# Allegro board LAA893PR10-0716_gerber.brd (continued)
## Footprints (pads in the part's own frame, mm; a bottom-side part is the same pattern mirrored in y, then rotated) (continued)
BELLW_80148-3221_67P-T
  round 1.092 hole 1.092 unplated: (-0.75,-5.275)
  round 1.6 hole 1.6 unplated: (19.25,-5.275)
  oval 0.305x1.549 smd: 1(0,0) 2(0.25,-7.55) 3(0.5,0) 4(0.75,-7.55) 5(1,0) 6(1.25,-7.55) 7(1.5,0) 8(3.75,-7.55) 9(4,0) 10(4.25,-7.55) 11(4.5,0) 12(4.75,-7.55) 13(5,0) 14(5.25,-7.55) 15(5.5,0) 16(5.75,-7.55) 17(6,0) 18(6.25,-7.55) 19(6.5,0) 20(6.75,-7.55) 21(7,0) 22(7.25,-7.55) 23(7.5,0) 24(7.75,-7.55) 25(8,0) 26(8.25,-7.55) 27(8.5,0) 28(8.75,-7.55) 29(9,0) 30(9.25,-7.55) 31(9.5,0) 32(9.75,-7.55) 33(10,0) 34(10.25,-7.55) 35(10.5,0) 36(10.75,-7.55) 37(11,0) 38(11.25,-7.55) 39(11.5,0) 40(11.75,-7.55) 41(12,0) 42(12.25,-7.55) 43(12.5,0) 44(12.75,-7.55) 45(13,0) 46(13.25,-7.55) 47(13.5,0) 48(13.75,-7.55) 49(14,0) 50(14.25,-7.55) 51(14.5,0) 52(14.75,-7.55) 53(15,0) 54(15.25,-7.55) 55(15.5,0) 56(15.75,-7.55) 57(16,0) 58(16.25,-7.55) 59(16.5,0) 60(16.75,-7.55) 61(17,0) 62(17.25,-7.55) 63(17.5,0) 64(17.75,-7.55) 65(18,0) 66(18.25,-7.55) 67(18.5,0)
  rect 1.194x2.743 smd: 68(-1.1,-0.775) 69(19.6,-0.775)
BQ24715URUYR_WQFN28_4X4
  oval 0.889x0.203 smd: 1(0,0) 2(0,-0.4) 3(0,-0.8) 4(0,-1.2) 5(0,-1.6) 6(0,-2) 7(0,-2.4) 15(4.1,-2.4) 16(4.1,-2) 17(4.1,-1.6) 18(4.1,-1.2) 19(4.1,-0.8) 20(4.1,-0.4) 21(4.1,0)
  oval 0.203x0.889 smd: 8(0.85,-3.25) 9(1.25,-3.25) 10(1.65,-3.25) 11(2.05,-3.25) 12(2.45,-3.25) 13(2.85,-3.25) 14(3.25,-3.25) 22(3.25,0.85) 23(2.85,0.85) 24(2.45,0.85) 25(2.05,0.85) 26(1.65,0.85) 27(1.25,0.85) 28(0.85,0.85)
  rect 2.591x2.591 smd: 29(2.05,-1.2)
C-K_26210-8K1A-02_9P-T
  round 1.118 hole 0.711: 1(0,0) 2(-2.5,0) 3(-4.5,0) 4(-7,0) 5(-7.5,-1.5) 6(-5.5,-1.5) 7(-3.5,-1.5) 8(-1.5,-1.5) 9(0.5,-1.5)
  oval 1.549x3.353 hole 0.787x2.591: 10(4.35,-2.43) 11(-11.35,-2.43)
  oval 1.549x2.464 hole 0.787x1.702: 12(-11.35,-9.23) 13(4.35,-9.23)
C_0402
  rect 0.508x0.559 smd: 1(0,0) 2(0.914,0)
C_0603
  rect 0.635x0.889 smd: 1(0,0) 2(1.397,0)
C_0805
  rect 0.813x1.397 smd: 1(0,0) 2(1.702,0)
C_1206
  rect 1.016x1.651 smd: 1(0,0) 2(2.667,0)
C_1808
  rect 1.041x2.311 smd: 1(0,0) 2(4.35,0)
C_APXK6R3ARA221MF451
  oval 3.15x1.6 smd: 1(0,0) 2(5.05,0)
C_D
  rect 2.388x2.896 smd: 1(0,0) 2(6.1,0)
C_D2
  rect 2.388x2.794 smd: 1(0,0) 2(6.4,0)
C_D3
  rect 2.388x2.794 smd: 1(0,0) 2(6.4,0)
CONCR_099BKAC19YBLCNF_19P-T
  round 0.813 hole 0.508: 1(0,0) 2(0.5,1.5) 3(1,0) 4(1.5,1.5) 5(2,0) 6(2.5,1.5) 7(3,0) 8(3.5,1.5) 9(4,0) 10(4.5,1.5) 11(5,0) 12(5.5,1.5) 13(6,0) 14(6.5,1.5) 15(7,0) 16(7.5,1.5) 17(8,0) 18(8.5,1.5) 19(9,0)
  oval 1.397x3.15 hole 0.787x2.54: 20(-2.75,0.9) 21(11.75,0.9)
  oval 1.803x2.794 hole 0.787x1.803: 22(-4.75,-6.08) 23(13.75,-6.08)
CSD97374CQ4M_SON8_3P5X4P5
  oval 0.203x0.889 smd: 1(0,0) 2(0.4,0) 3(0.8,0) 6(0.8,3.5) 7(0.4,3.5) 8(0,3.5)
  custom 0.225x0.225 smd: 4(2.2,0.262) 5(2.2,3.238)
  rect 4.039x2.21 smd: 9(1.6,1.75)
DCX124EK-7-F_SC74R-6
  oval 0.559x0.787 smd: 1(0,0) 2(-0.95,0) 3(-1.9,0) 4(-1.9,2.4) 5(-0.95,2.4) 6(0,2.4)
DDTA114EUA-7-F_SOT323-3
  oval 0.813x0.914 smd: 1(0,0) 2(0.65,1.6) 3(-0.65,1.6)
DEREN_40-42251-01001RHF_10P-T
  oval 0.838x2.21 smd: 1(0,0.1) 2(1.5,0.1) 3(3,0.1) 4(4.5,0.1) 5(6,0.1) 6(7.5,0.1) 7(9,0.1) 8(10.5,0.1) 9(12,0.1) 10(13.5,0.1)
  custom 0.75x0.75 smd: 11(-3.4,-3.15) 12(16.9,-3.15)
DMN65D8LW-7_SOT323-3
  oval 0.711x0.889 smd: 1(0,0) 2(-0.65,-1.9) 3(0.65,-1.9)
DMN66D0LDW-7_SOT363-6
  oval 0.432x0.61 smd: 1(0,0) 2(0.65,0) 3(1.3,0) 4(1.3,1.9) 5(0.65,1.9) 6(0,1.9)
E-T_6700K-Y20N-00L_20P
  oval 0.61x1.499 smd: 1(0,0) 2(-0.5,-2.8) 3(-1,0) 4(-1.5,-2.8) 5(-2,0) 6(-2.5,-2.8) 7(-3,0) 8(-3.5,-2.8) 9(-4,0) 10(-4.5,-2.8) 11(-5,0) 12(-5.5,-2.8) 13(-6,0) 14(-6.5,-2.8) 15(-7,0) 16(-7.5,-2.8) 17(-8,0) 18(-8.5,-2.8) 19(-9,0) 20(-9.5,-2.8)
  rect 0.787x1.499 smd: 21(1,0) 22(1,-2.8) 23(-10.5,0) 24(-10.5,-2.8)
E-T_6705K-Y10N-00L_10P-T
  oval 0.305x1.092 smd: 1(0,0) 2(0.5,0) 3(1,0) 4(1.5,0) 5(2,0) 6(2.5,0) 7(3,0) 8(3.5,0) 9(4,0) 10(4.5,0)
  rect 0.991x2.007 smd: 11(-2.1,-3.15) 12(6.6,-3.15)
E-T_6705K-Y16N-00L_16P
  oval 0.305x1.092 smd: 1(0,0) 2(0.5,0) 3(1,0) 4(1.5,0) 5(2,0) 6(2.5,0) 7(3,0) 8(3.5,0) 9(4,0) 10(4.5,0) 11(5,0) 12(5.5,0) 13(6,0) 14(6.5,0) 15(7,0) 16(7.5,0)
  rect 0.991x2.007 smd: 17(-2.1,-3.15) 18(9.6,-3.15)
ECE1099-FZG_QFN40_6X6
  oval 0.254x1.041 smd: 1(0,0) 2(0.5,0) 3(1,0) 4(1.5,0) 5(2,0) 6(2.5,0) 7(3,0) 8(3.5,0) 9(4,0) 10(4.5,0) 21(4.5,5.95) 22(4,5.95) 23(3.5,5.95) 24(3,5.95) 25(2.5,5.95) 26(2,5.95) 27(1.5,5.95) 28(1,5.95) 29(0.5,5.95) 30(0,5.95)
  oval 1.041x0.254 smd: 11(5.225,0.725) 12(5.225,1.225) 13(5.225,1.725) 14(5.225,2.225) 15(5.225,2.725) 16(5.225,3.225) 17(5.225,3.725) 18(5.225,4.225) 19(5.225,4.725) 20(5.225,5.225) 31(-0.725,5.225) 32(-0.725,4.725) 33(-0.725,4.225) 34(-0.725,3.725) 35(-0.725,3.225) 36(-0.725,2.725) 37(-0.725,2.225) 38(-0.725,1.725) 39(-0.725,1.225) 40(-0.725,0.725)
  rect 4.089x4.089 smd: 41(2.25,2.975)
FDV301N-G_SOT23-3
  oval 1.016x1.524 smd: 1(0,0) 2(0.965,2.083) 3(-0.965,2.083)
FIDUCIAL_C40M80
  round 1.016 smd: 1(0,0)
G547I2P81U_MSOP8
  oval 0.381x1.549 smd: 1(0,0) 2(0.65,0) 3(1.3,0) 4(1.95,0) 5(1.95,4.37) 6(1.3,4.37) 7(0.65,4.37) 8(0,4.37)
H_2P3
  round 2.819 hole 2.311: 1(0,0)
H_2P6N
  round 2.591 hole 2.591 unplated: (0,0)
H_3P2
  round 3.708 hole 3.2: 1(0,0)
H_3P3
  round 3.81 hole 3.302: 1(0,0)
H_3P5
  round 4.013 hole 3.505: 1(0,0)
H_3P6
  round 4.115 hole 3.607: 1(0,0)
H_5P2X2P6N
  oval 5.207x2.591 hole 5.207x2.591 unplated: (0,0)
H_5P5N
  round 5.512 hole 5.512 unplated: (0,0)
HB_A531015-SCHR21_10P
  oval 0.305x0.889 smd: 1(0,0) 2(0.5,0) 3(1,0) 4(1.5,0) 5(2,0) 6(2.5,0) 7(3,0) 8(3.5,0) 9(4,0) 10(4.5,0)
  rect 0.991x2.007 smd: 11(6.6,-3.05) 12(-2.1,-3.05)
JUMP_43X39
  custom 0.191x0.191 smd: 1(0,0) 2(0.914,0)
JUMP_43X79
  custom 0.188x0.188 smd: 1(0,0) 2(1.1,0)
JUMP_43X118
  custom 0.187x0.187 smd: 1(0,0) 2(1.1,0)
JUMP_43X118-NPM
  custom 0.187x0.187 smd: 1(0,0) 2(1.1,0)
KC_FBMA-L11-453215800LMA90T_2P
  rect 1.803x3.404 smd: 1(0,0) 2(3.8,0)
KNOW_SPM1437HM4H-6_6P
  round 0.914 smd: 1(0,0) 2(0,-1.65) 3(0,-3.3) 4(2.34,-3.3) 5(2.34,-1.65)
  oval 0.914x1.194 smd rot 135: 6(2.24,-0.1)
L2N7002WT1G_SC-70-3
  oval 0.711x0.889 smd: 1(0,0) 2(-0.65,-1.9) 3(0.65,-1.9)
L03ESDL5V0CC3-2_SOT23-3
  oval 1.016x1.524 smd: 1(0,0) 2(0.965,2.083) 3(-0.965,2.083)
L05ESDL5V0NA-4_SLP2510P8-10-9
  rect 0.203x0.686 smd: 1(0,0) 2(-0.5,0) 4(-1.5,0) 5(-2,0) 6(-2,-0.875) 7(-1.5,-0.875) 8(-0.5,-0.875) 9(0,-0.875)
  rect 0.406x1.549 smd: 3(-1,-0.437)
L_5X5X3_M_2P
  rect 2.159x2.794 smd: 1(0,0) 2(4.35,0)
L_5X5X3_M_2P-NPM
  rect 2.159x2.794 smd: 1(0,0) 2(4.35,0)
LCN_DAN06-K4406-0103_204P
  round 1.092 hole 1.092 unplated: (-65.05,-4.1)
  round 1.6 hole 1.6 unplated: (1.75,-4.1)
  oval 0.356x2.007 smd: 1(0,0) 2(-0.3,-8.2) 3(-0.6,0) 4(-0.9,-8.2) 5(-1.2,0) 6(-1.5,-8.2) 7(-1.8,0) 8(-2.1,-8.2) 9(-2.4,0) 10(-2.7,-8.2) 11(-3,0) 12(-3.3,-8.2) 13(-3.6,0) 14(-3.9,-8.2) 15(-4.2,0) 16(-4.5,-8.2) 17(-4.8,0) 18(-5.1,-8.2) 19(-5.4,0) 20(-5.7,-8.2) 21(-6,0) 22(-6.3,-8.2) 23(-6.6,0) 24(-6.9,-8.2) 25(-7.2,0) 26(-7.5,-8.2) 27(-7.8,0) 28(-8.1,-8.2) 29(-8.4,0) 30(-8.7,-8.2) 31(-9,0) 32(-9.3,-8.2) 33(-9.6,0) 34(-9.9,-8.2) 35(-10.2,0) 36(-10.5,-8.2) 37(-10.8,0) 38(-11.1,-8.2) 39(-11.4,0) 40(-11.7,-8.2) 41(-12,0) 42(-12.3,-8.2) 43(-12.6,0) 44(-12.9,-8.2) 45(-13.2,0) 46(-13.5,-8.2) 47(-13.8,0) 48(-14.1,-8.2) 49(-14.4,0) 50(-14.7,-8.2) 51(-15,0) 52(-15.3,-8.2) 53(-15.6,0) 54(-15.9,-8.2) 55(-16.2,0) 56(-16.5,-8.2) 57(-16.8,0) 58(-17.1,-8.2) 59(-17.4,0) 60(-17.7,-8.2) 61(-18,0) 62(-18.3,-8.2) 63(-18.6,0) 64(-18.9,-8.2) 65(-19.2,0) 66(-19.5,-8.2) 67(-19.8,0) 68(-20.1,-8.2) 69(-20.4,0) 70(-20.7,-8.2) 71(-21,0) 72(-21.3,-8.2) 73(-24,0) 74(-24.3,-8.2) 75(-24.6,0) 76(-24.9,-8.2) 77(-25.2,0) 78(-25.5,-8.2) 79(-25.8,0) 80(-26.1,-8.2) 81(-26.4,0) 82(-26.7,-8.2) 83(-27,0) 84(-27.3,-8.2) 85(-27.6,0) 86(-27.9,-8.2) 87(-28.2,0) 88(-28.5,-8.2) 89(-28.8,0) 90(-29.1,-8.2) 91(-29.4,0) 92(-29.7,-8.2) 93(-30,0) 94(-30.3,-8.2) 95(-30.6,0) 96(-30.9,-8.2) 97(-31.2,0) 98(-31.5,-8.2) 99(-31.8,0) 100(-32.1,-8.2) 101(-32.4,0) 102(-32.7,-8.2) 103(-33,0) 104(-33.3,-8.2) 105(-33.6,0) 106(-33.9,-8.2) 107(-34.2,0) 108(-34.5,-8.2) 109(-34.8,0) 110(-35.1,-8.2) 111(-35.4,0) 112(-35.7,-8.2) 113(-36,0) 114(-36.3,-8.2) 115(-36.6,0) 116(-36.9,-8.2) 117(-37.2,0) 118(-37.5,-8.2) 119(-37.8,0) 120(-38.1,-8.2) 121(-38.4,0) 122(-38.7,-8.2) 123(-39,0) 124(-39.3,-8.2) 125(-39.6,0) 126(-39.9,-8.2) 127(-40.2,0) 128(-40.5,-8.2) 129(-40.8,0) 130(-41.1,-8.2) 131(-41.4,0) 132(-41.7,-8.2) 133(-42,0) 134(-42.3,-8.2) 135(-42.6,0) 136(-42.9,-8.2) 137(-43.2,0) 138(-43.5,-8.2) 139(-43.8,0) 140(-44.1,-8.2) 141(-44.4,0) 142(-44.7,-8.2) 143(-45,0) 144(-45.3,-8.2) 145(-45.6,0) 146(-45.9,-8.2) 147(-46.2,0) 148(-46.5,-8.2) 149(-46.8,0) 150(-47.1,-8.2) 151(-47.4,0) 152(-47.7,-8.2) 153(-48,0) 154(-48.3,-8.2) 155(-48.6,0) 156(-48.9,-8.2) 157(-49.2,0) 158(-49.5,-8.2) 159(-49.8,0) 160(-50.1,-8.2) 161(-50.4,0) 162(-50.7,-8.2) 163(-51,0) 164(-51.3,-8.2) 165(-51.6,0) 166(-51.9,-8.2) 167(-52.2,0) 168(-52.5,-8.2) 169(-52.8,0) 170(-53.1,-8.2) 171(-53.4,0) 172(-53.7,-8.2) 173(-54,0) 174(-54.3,-8.2) 175(-54.6,0) 176(-54.9,-8.2) 177(-55.2,0) 178(-55.5,-8.2) 179(-55.8,0) 180(-56.1,-8.2) 181(-56.4,0) 182(-56.7,-8.2) 183(-57,0) 184(-57.3,-8.2) 185(-57.6,0) 186(-57.9,-8.2) 187(-58.2,0) 188(-58.5,-8.2) 189(-58.8,0) 190(-59.1,-8.2) 191(-59.4,0) 192(-59.7,-8.2) 193(-60,0) 194(-60.3,-8.2) 195(-60.6,0) 196(-60.9,-8.2) 197(-61.2,0) 198(-61.5,-8.2) 199(-61.8,0) 200(-62.1,-8.2) 201(-62.4,0) 202(-62.7,-8.2) 203(-63,0) 204(-63.3,-8.2)
  rect 3.505x4.597 smd: 205(1.15,7.9) 206(-64.45,7.9)
LCN_DAN06-K4406-0103_204P-S
  round 1.092 hole 1.092 unplated: (-65.05,-4.1)
  round 1.6 hole 1.6 unplated: (1.75,-4.1)
  oval 0.356x2.007 smd: 1(0,0) 2(-0.3,-8.2) 3(-0.6,0) 4(-0.9,-8.2) 5(-1.2,0) 6(-1.5,-8.2) 7(-1.8,0) 8(-2.1,-8.2) 9(-2.4,0) 10(-2.7,-8.2) 11(-3,0) 12(-3.3,-8.2) 13(-3.6,0) 14(-3.9,-8.2) 15(-4.2,0) 16(-4.5,-8.2) 17(-4.8,0) 18(-5.1,-8.2) 19(-5.4,0) 20(-5.7,-8.2) 21(-6,0) 22(-6.3,-8.2) 23(-6.6,0) 24(-6.9,-8.2) 25(-7.2,0) 26(-7.5,-8.2) 27(-7.8,0) 28(-8.1,-8.2) 29(-8.4,0) 30(-8.7,-8.2) 31(-9,0) 32(-9.3,-8.2) 33(-9.6,0) 34(-9.9,-8.2) 35(-10.2,0) 36(-10.5,-8.2) 37(-10.8,0) 38(-11.1,-8.2) 39(-11.4,0) 40(-11.7,-8.2) 41(-12,0) 42(-12.3,-8.2) 43(-12.6,0) 44(-12.9,-8.2) 45(-13.2,0) 46(-13.5,-8.2) 47(-13.8,0) 48(-14.1,-8.2) 49(-14.4,0) 50(-14.7,-8.2) 51(-15,0) 52(-15.3,-8.2) 53(-15.6,0) 54(-15.9,-8.2) 55(-16.2,0) 56(-16.5,-8.2) 57(-16.8,0) 58(-17.1,-8.2) 59(-17.4,0) 60(-17.7,-8.2) 61(-18,0) 62(-18.3,-8.2) 63(-18.6,0) 64(-18.9,-8.2) 65(-19.2,0) 66(-19.5,-8.2) 67(-19.8,0) 68(-20.1,-8.2) 69(-20.4,0) 70(-20.7,-8.2) 71(-21,0) 72(-21.3,-8.2) 73(-24,0) 74(-24.3,-8.2) 75(-24.6,0) 76(-24.9,-8.2) 77(-25.2,0) 78(-25.5,-8.2) 79(-25.8,0) 80(-26.1,-8.2) 81(-26.4,0) 82(-26.7,-8.2) 83(-27,0) 84(-27.3,-8.2) 85(-27.6,0) 86(-27.9,-8.2) 87(-28.2,0) 88(-28.5,-8.2) 89(-28.8,0) 90(-29.1,-8.2) 91(-29.4,0) 92(-29.7,-8.2) 93(-30,0) 94(-30.3,-8.2) 95(-30.6,0) 96(-30.9,-8.2) 97(-31.2,0) 98(-31.5,-8.2) 99(-31.8,0) 100(-32.1,-8.2) 101(-32.4,0) 102(-32.7,-8.2) 103(-33,0) 104(-33.3,-8.2) 105(-33.6,0) 106(-33.9,-8.2) 107(-34.2,0) 108(-34.5,-8.2) 109(-34.8,0) 110(-35.1,-8.2) 111(-35.4,0) 112(-35.7,-8.2) 113(-36,0) 114(-36.3,-8.2) 115(-36.6,0) 116(-36.9,-8.2) 117(-37.2,0) 118(-37.5,-8.2) 119(-37.8,0) 120(-38.1,-8.2) 121(-38.4,0) 122(-38.7,-8.2) 123(-39,0) 124(-39.3,-8.2) 125(-39.6,0) 126(-39.9,-8.2) 127(-40.2,0) 128(-40.5,-8.2) 129(-40.8,0) 130(-41.1,-8.2) 131(-41.4,0) 132(-41.7,-8.2) 133(-42,0) 134(-42.3,-8.2) 135(-42.6,0) 136(-42.9,-8.2) 137(-43.2,0) 138(-43.5,-8.2) 139(-43.8,0) 140(-44.1,-8.2) 141(-44.4,0) 142(-44.7,-8.2) 143(-45,0) 144(-45.3,-8.2) 145(-45.6,0) 146(-45.9,-8.2) 147(-46.2,0) 148(-46.5,-8.2) 149(-46.8,0) 150(-47.1,-8.2) 151(-47.4,0) 152(-47.7,-8.2) 153(-48,0) 154(-48.3,-8.2) 155(-48.6,0) 156(-48.9,-8.2) 157(-49.2,0) 158(-49.5,-8.2) 159(-49.8,0) 160(-50.1,-8.2) 161(-50.4,0) 162(-50.7,-8.2) 163(-51,0) 164(-51.3,-8.2) 165(-51.6,0) 166(-51.9,-8.2) 167(-52.2,0) 168(-52.5,-8.2) 169(-52.8,0) 170(-53.1,-8.2) 171(-53.4,0) 172(-53.7,-8.2) 173(-54,0) 174(-54.3,-8.2) 175(-54.6,0) 176(-54.9,-8.2) 177(-55.2,0) 178(-55.5,-8.2) 179(-55.8,0) 180(-56.1,-8.2) 181(-56.4,0) 182(-56.7,-8.2) 183(-57,0) 184(-57.3,-8.2) 185(-57.6,0) 186(-57.9,-8.2) 187(-58.2,0) 188(-58.5,-8.2) 189(-58.8,0) 190(-59.1,-8.2) 191(-59.4,0) 192(-59.7,-8.2) 193(-60,0) 194(-60.3,-8.2) 195(-60.6,0) 196(-60.9,-8.2) 197(-61.2,0) 198(-61.5,-8.2) 199(-61.8,0) 200(-62.1,-8.2) 201(-62.4,0) 202(-62.7,-8.2) 203(-63,0) 204(-63.3,-8.2)
  rect 3.505x4.597 smd: 205(1.15,7.9) 206(-64.45,7.9)
LED_LTW-193ZDS5_2P
  rect 0.787x0.787 smd: 1(0,0) 2(1.5,0)
LNG3DMTR_LGA16_3X3
  oval 0.305x0.864 smd: 1(0,0) 2(0.5,0) 3(1,0) 4(1.5,0) 5(2,0) 9(2,2.96) 10(1.5,2.96) 11(1,2.96) 12(0.5,2.96) 13(0,2.96)
  oval 0.864x0.305 smd: 6(2.48,0.98) 7(2.48,1.48) 8(2.48,1.98) 14(-0.48,1.98) 15(-0.48,1.48) 16(-0.48,0.98)
LP2301ALT1G_SOT23-3
  oval 1.016x1.524 smd: 1(0,0) 2(0.965,2.083) 3(-0.965,2.083)
MEC5085-LZY_DQFN132_11X11
  oval 0.279x0.711 smd: A1(0,0) A2(0.5,0) A3(1,0) A4(1.5,0) A5(2,0) A6(2.5,0) A7(3,0) A8(3.5,0) A9(4,0) A10(4.5,0) A11(5,0) A12(5.5,0) A13(6,0) A14(6.5,0) A15(7,0) A16(7.5,0) A33(7.5,10.9) A34(7,10.9) A35(6.5,10.9) A36(6,10.9) A37(5.5,10.9) A38(5,10.9) A39(4.5,10.9) A40(4,10.9) A41(3.5,10.9) A42(3,10.9) A43(2.5,10.9) A44(2,10.9) A45(1.5,10.9) A46(1,10.9) A47(0.5,10.9) A48(0,10.9)
  oval 0.711x0.279 smd: A17(9.2,1.7) A18(9.2,2.2) A19(9.2,2.7) A20(9.2,3.2) A21(9.2,3.7) A22(9.2,4.2) A23(9.2,4.7) A24(9.2,5.2) A25(9.2,5.7) A26(9.2,6.2) A27(9.2,6.7) A28(9.2,7.2) A29(9.2,7.7) A30(9.2,8.2) A31(9.2,8.7) A32(9.2,9.2) A49(-1.7,9.2) A50(-1.7,8.7) A51(-1.7,8.2) A52(-1.7,7.7) A53(-1.7,7.2) A54(-1.7,6.7) A55(-1.7,6.2) A56(-1.7,5.7) A57(-1.7,5.2) A58(-1.7,4.7) A59(-1.7,4.2) A60(-1.7,3.7) A61(-1.7,3.2) A62(-1.7,2.7) A63(-1.7,2.2) A64(-1.7,1.7)
  oval 0.305x0.61 smd: B1(-0.25,0.85) B2(0.25,0.85) B3(0.75,0.85) B4(1.25,0.85) B5(1.75,0.85) B6(2.25,0.85) B7(2.75,0.85) B8(3.25,0.85) B9(3.75,0.85) B10(4.25,0.85) B11(4.75,0.85) B12(5.25,0.85) B13(5.75,0.85) B14(6.25,0.85) B15(6.75,0.85) B16(7.25,0.85) B17(7.75,0.85) B35(7.75,10.05) B36(7.25,10.05) B37(6.75,10.05) B38(6.25,10.05) B39(5.75,10.05) B40(5.25,10.05) B41(4.75,10.05) B42(4.25,10.05) B43(3.75,10.05) B44(3.25,10.05) B45(2.75,10.05) B46(2.25,10.05) B47(1.75,10.05) B48(1.25,10.05) B49(0.75,10.05) B50(0.25,10.05) B51(-0.25,10.05)
  oval 0.61x0.305 smd: B18(8.35,1.45) B19(8.35,1.95) B20(8.35,2.45) B21(8.35,2.95) B22(8.35,3.45) B23(8.35,3.95) B24(8.35,4.45) B25(8.35,4.95) B26(8.35,5.45) B27(8.35,5.95) B28(8.35,6.45) B29(8.35,6.95) B30(8.35,7.45) B31(8.35,7.95) B32(8.35,8.45) B33(8.35,8.95) B34(8.35,9.45) B52(-0.85,9.45) B53(-0.85,8.95) B54(-0.85,8.45) B55(-0.85,7.95) B56(-0.85,7.45) B57(-0.85,6.95) B58(-0.85,6.45) B59(-0.85,5.95) B60(-0.85,5.45) B61(-0.85,4.95) B62(-0.85,4.45) B63(-0.85,3.95) B64(-0.85,3.45) B65(-0.85,2.95) B66(-0.85,2.45) B67(-0.85,1.95) B68(-0.85,1.45)
  rect 5.004x5.004 smd: C1(3.75,5.45)
MHPC_NS692417_24P
  oval 0.762x2.057 smd: 1(0,0) 2(1.27,0) 3(2.54,0) 4(3.81,0) 5(5.08,0) 6(6.35,0) 7(7.62,0) 8(8.89,0) 9(10.16,0) 10(11.43,0) 11(12.7,0) 12(13.97,0) 13(13.97,9.365) 14(12.7,9.365) 15(11.43,9.365) 16(10.16,9.365) 17(8.89,9.365) 18(7.62,9.365) 19(6.35,9.365) 20(5.08,9.365) 21(3.81,9.365) 22(2.54,9.365) 23(1.27,9.365) 24(0,9.365)
MMBT3904WT1G_SC70-3
  oval 0.711x0.889 smd: 1(0,0) 2(0.65,1.9) 3(-0.65,1.9)
MMST3904-7-F_SOT323-3
  oval 0.711x0.889 smd: 1(0,0) 2(0.65,1.9) 3(-0.65,1.9)
MURAT_BLM15AG102SN1D_2P
  rect 0.457x0.508 smd: 1(0,0) 2(0.85,0)
MURAT_BLM15BB221SN1D_2P
  rect 0.508x0.762 smd: 1(0,0) 2(0.75,0)
MURAT_BLM15BD601SN1D_2P
  rect 0.508x0.762 smd: 1(0,0) 2(0.75,0)
MURAT_BLM15PX330SN1D_2P
  rect 0.508x0.762 smd: 1(0,0) 2(0.75,0)
MURAT_BLM15PX600SN1D_2P
  rect 0.457x0.508 smd: 1(0,0) 2(0.85,0)
MURAT_DLW21HN900HQ2L_4P
  rect 0.889x0.356 smd: 1(0,0) 2(1.7,0) 3(1.7,0.85) 4(0,0.85)
MURAT_LQM2MPN2R2NG0L_2P
  rect 0.787x1.803 smd: 1(0,0) 2(1.6,0)
OZ777FJ2LN_QFN48_6X6
  oval 0.203x0.889 smd: 1(0,0) 2(0.4,0) 3(0.8,0) 4(1.2,0) 5(1.6,0) 6(2,0) 7(2.4,0) 8(2.8,0) 9(3.2,0) 10(3.6,0) 11(4,0) 12(4.4,0) 25(4.4,6.1) 26(4,6.1) 27(3.6,6.1) 28(3.2,6.1) 29(2.8,6.1) 30(2.4,6.1) 31(2,6.1) 32(1.6,6.1) 33(1.2,6.1) 34(0.8,6.1) 35(0.4,6.1) 36(0,6.1)
  oval 0.889x0.203 smd: 13(5.25,0.85) 14(5.25,1.25) 15(5.25,1.65) 16(5.25,2.05) 17(5.25,2.45) 18(5.25,2.85) 19(5.25,3.25) 20(5.25,3.65) 21(5.25,4.05) 22(5.25,4.45) 23(5.25,4.85) 24(5.25,5.25) 37(-0.85,5.25) 38(-0.85,4.85) 39(-0.85,4.45) 40(-0.85,4.05) 41(-0.85,3.65) 42(-0.85,3.25) 43(-0.85,2.85) 44(-0.85,2.45) 45(-0.85,2.05) 46(-0.85,1.65) 47(-0.85,1.25) 48(-0.85,0.85)
  rect 4.343x4.343 smd: 49(2.2,3.05)
PANAS_ETQP3W2R2WFN_2P
  rect 2.362x3.505 smd: 1(0,0) 2(-6.05,0)
PANAS_ETQP4LR15AFM_4P
  custom 0.686x0.686 smd: 1(0,0) 4(8.357,0)
  rect 2.21x0.508 smd: 2(1.448,0) 3(6.909,0)
PDS5100H-13_POWERDI5-3
  rect 4.851x3.353 smd: 1(0,0)
  rect 1.397x1.397 smd: 2(3.982,-0.92) 3(3.982,0.92)
PI3C3125LEX_TSSOP14
  oval 0.381x1.626 smd: 1(0,0) 2(0.65,0) 3(1.3,0) 4(1.95,0) 5(2.6,0) 6(3.25,0) 7(3.9,0) 8(3.9,5.8) 9(3.25,5.8) 10(2.6,5.8) 11(1.95,5.8) 12(1.3,5.8) 13(0.65,5.8) 14(0,5.8)
PI3EQX6741STZDEX_TQFN20_4X4
  oval 0.254x1.143 smd: 1(0,0) 2(0.5,0) 3(1,0) 4(1.5,0) 5(2,0) 11(2,3.851) 12(1.5,3.851) 13(1,3.851) 14(0.5,3.851) 15(0,3.851)
  oval 1.143x0.254 smd: 6(2.925,0.925) 7(2.925,1.425) 8(2.925,1.925) 9(2.925,2.425) 10(2.925,2.925) 16(-0.925,2.925) 17(-0.925,2.425) 18(-0.925,1.925) 19(-0.925,1.425) 20(-0.925,0.925)
  rect 2.108x2.108 smd: 21(1,1.925)
PS8339BQFN56GTR2-A0_QFN56_7X7
  oval 0.203x1.041 smd: 1(0,0) 2(0.4,0) 3(0.8,0) 4(1.2,0) 5(1.6,0) 6(2,0) 7(2.4,0) 8(2.8,0) 9(3.2,0) 10(3.6,0) 11(4,0) 12(4.4,0) 13(4.8,0) 14(5.2,0) 29(5.2,6.95) 30(4.8,6.95) 31(4.4,6.95) 32(4,6.95) 33(3.6,6.95) 34(3.2,6.95) 35(2.8,6.95) 36(2.4,6.95) 37(2,6.95) 38(1.6,6.95) 39(1.2,6.95) 40(0.8,6.95) 41(0.4,6.95) 42(0,6.95)
  oval 1.041x0.203 smd: 15(6.075,0.875) 16(6.075,1.275) 17(6.075,1.675) 18(6.075,2.075) 19(6.075,2.475) 20(6.075,2.875) 21(6.075,3.275) 22(6.075,3.675) 23(6.075,4.075) 24(6.075,4.475) 25(6.075,4.875) 26(6.075,5.275) 27(6.075,5.675) 28(6.075,6.075) 43(-0.875,6.075) 44(-0.875,5.675) 45(-0.875,5.275) 46(-0.875,4.875) 47(-0.875,4.475) 48(-0.875,4.075) 49(-0.875,3.675) 50(-0.875,3.275) 51(-0.875,2.875) 52(-0.875,2.475) 53(-0.875,2.075) 54(-0.875,1.675) 55(-0.875,1.275) 56(-0.875,0.875)
  rect 4.699x3.912 smd: 57(2.6,3.475)
R0402_0OHM
  rect 0.508x0.559 smd: 1(0,0) 2(0.914,0)
R0603_0OHM
  rect 0.635x0.889 smd: 1(0,0) 2(1.397,0)
R0805_0OHM
  rect 0.813x1.397 smd: 1(0,0) 2(1.702,0)
R_0402
  rect 0.508x0.559 smd: 1(0,0) 2(0.914,0)
R_0603
  rect 0.635x0.889 smd: 1(0,0) 2(1.397,0)
R_0805
  rect 0.813x1.397 smd: 1(0,0) 2(1.702,0)
R_1206
  rect 1.016x1.651 smd: 1(0,0) 2(2.667,0)
R_1206_4P-D
  custom 0.445x0.445 smd: 1(0,0) 4(5.004,0)
  custom 0.114x0.114 smd: 2(1.194,0) 3(3.81,0)
RB751S40T1G_SOD523-2
  rect 0.406x0.406 smd: 1(0,0) 2(1.4,0)
RP_0804_8P4R
  oval 0.66x0.254 smd: 1(0,0) 2(0,-0.5) 3(0,-1) 4(0,-1.5) 5(1.15,-1.5) 6(1.15,-1) 7(1.15,-0.5) 8(1.15,0)
RT8207MZQW_WQFN20_3X3
  oval 0.203x0.889 smd: 1(0,0) 2(0.4,0) 3(0.8,0) 4(1.2,0) 5(1.6,0) 11(1.6,3.1) 12(1.2,3.1) 13(0.8,3.1) 14(0.4,3.1) 15(0,3.1)
  oval 0.889x0.203 smd: 6(2.35,0.75) 7(2.35,1.15) 8(2.35,1.55) 9(2.35,1.95) 10(2.35,2.35) 16(-0.75,2.35) 17(-0.75,1.95) 18(-0.75,1.55) 19(-0.75,1.15) 20(-0.75,0.75)
  rect 1.702x1.702 smd: 21(0.8,1.55)
RT9818A-44GU3_SC70-3
  oval 0.61x0.787 smd: 1(0,0) 2(-0.65,-1.9) 3(0.65,-1.9)
SAMTE_BSH-030-01-L-D-A_60P
  round 1.016 hole 1.016 unplated: (-2.81,5.53) (17.316,5.53)
  oval 0.279x2.261 smd: 1(0,0) 2(0,5.728) 3(0.5,0) 4(0.5,5.728) 5(1,0) 6(1,5.728) 7(1.5,0) 8(1.5,5.728) 9(2,0) 10(2,5.728) 11(2.5,0) 12(2.5,5.728) 13(3,0) 14(3,5.728) 15(3.5,0) 16(3.5,5.728) 17(4,0) 18(4,5.728) 19(4.5,0) 20(4.5,5.728) 21(5,0) 22(5,5.728) 23(5.5,0) 24(5.5,5.728) 25(6,0) 26(6,5.728) 27(6.5,0) 28(6.5,5.728) 29(7,0) 30(7,5.728) 31(7.5,0) 32(7.5,5.728) 33(8,0) 34(8,5.728) 35(8.5,0) 36(8.5,5.728) 37(9,0) 38(9,5.728) 39(9.5,0) 40(9.5,5.728) 41(10,0) 42(10,5.728) 43(10.5,0) 44(10.5,5.728) 45(11,0) 46(11,5.728) 47(11.5,0) 48(11.5,5.728) 49(12,0) 50(12,5.728) 51(12.5,0) 52(12.5,5.728) 53(13,0) 54(13,5.728) 55(13.5,0) 56(13.5,5.728) 57(14,0) 58(14,5.728) 59(14.5,0) 60(14.5,5.728)
SANTA_130456-511_13P-T
  round 1.295 hole 0.889: 1(0,0) 2(1.02,1.1) 3(2.04,0) 4(3.06,1.1) 5(4.08,0) 6(5.1,1.1) 7(6.12,0) 8(7.14,1.1)
  round 1.397 hole 0.991: 9(-3.395,1.1) 10(-1.105,2.6) 11(8.245,2.6) 12(9.39,1.1) 13(10.535,2.6)
  oval 1.473x3.15 hole 0.711x2.388: 14(13.095,-6.42) 16(-5.955,-6.42)
  rect 0.889x1.803 smd: 15(12.32,-9.92) 17(-5.18,-9.92)
SDMK0340L-7-F_SOD323-2
  rect 1.346x0.66 smd: 1(0,0) 2(2.4,0)
SHORTPADS
  custom 0.19x0.19 smd: 1(-0.483,0) 2(0.483,0)
SHORTPADS-S
  custom 0.19x0.19 smd: 1(-0.483,0) 2(0.483,0)
SI3456DDV-T1-GE3_TSOP6
  oval 0.508x1.422 smd: 1(0,0) 2(0.95,0) 3(1.9,0) 4(1.9,2.44) 5(0.95,2.44) 6(0,2.44)
SI4835DDY-T1-E3_SO8
  oval 0.635x1.727 smd: 1(0,0) 2(1.27,0) 3(2.54,0) 4(3.81,0) 5(3.81,5.285) 6(2.54,5.285) 7(1.27,5.285) 8(0,5.285)
SI7716ADN-T1-GE3_POWERPAK8-5
  oval 0.406x0.991 smd: 1(0,0) 2(0.66,0) 3(1.32,0) 4(1.98,0)
  custom 0.559x0.559 smd: 5(0.99,2.247)
SINGA_2SJ3080-039111F_6P-T
  oval 1.092x1.905 hole 0.61x1.397: 1(0,0) 2(-9.5,5.5) 3(0,7.8) 4(-9.5,8.4) 5(-9.5,0) 6(-9.5,2.75) 7(0,4.1)
SINGA_2UB1641-000111F_9P-T
  round 1.295 hole 0.711: 1(0,0) 2(-2.5,0) 3(-4.5,0) 4(-7,0) 5(-7.5,-1.5) 6(-5.5,-1.5) 7(-3.5,-1.5) 8(-1.5,-1.5) 9(0.5,-1.5)
  oval 1.295x2.311 hole 0.711x1.702: 10(-9.9,0.3) 11(2.9,0.3)
  oval 1.194x2.007 hole 0.61x1.397: 12(-11.2,-8.95) 13(4.2,-8.95)
SIS412DN-T1-GE3_POWERPAK8-5
  oval 0.406x0.991 smd: 1(0,0) 2(0.66,0) 3(1.32,0) 4(1.98,0)
  custom 0.559x0.559 smd: 5(0.99,2.247)
STARC_115B20-000000-G2-R_20P-T
  round 0.889 hole 0.889 unplated: (-1.05,2.325) (10.55,2.325)
  oval 0.254x1.143 smd: 1(0,0) 2(0.5,0) 3(1,0) 4(1.5,0) 5(2,0) 6(2.5,0) 7(3,0) 8(3.5,0) 9(4,0) 10(4.5,0) 11(5,0) 12(5.5,0) 13(6,0) 14(6.5,0) 15(7,0) 16(7.5,0) 17(8,0) 18(8.5,0) 19(9,0) 20(9.5,0)
  rect 1.295x1.397 smd: 21(10.55,0.125) 22(10.55,4.125) 23(-1.05,4.125) 24(-1.05,0.125)
SW_SKRBAAE010_4P
  rect 0.889x1.219 smd: 1(0,0) 2(3.9,0) 3(0,4.075) 4(3.9,4.075)
SW_SS3-CMFTQR9_3P
  oval 0.991x2.489 smd: 1(0,0) 2(2,0) 3(4,0)
  round 1.651 hole 0.889: 4(-0.15,-3.75) 5(6.15,-3.75)
SY8208DQNC_QFN10_3X3
  oval 0.254x0.61 smd: 1(0,0) 2(0.45,0) 3(0.9,0) 4(1.35,0) 5(1.8,0) 6(2.25,0)
  rect 1.168x0.254 smd: 7(2.19,-0.675)
  rect 0.914x2.007 smd: 8(2.065,-2)
  custom 0.482x0.482 smd: 9(1.077,-1.775)
  rect 0.813x1.168 smd: 10(0.137,-1.587)
T-SOL_156-2000302608_19P_NR-S
  round 0.889 hole 0.889 unplated: (-7.075,-28.925) (13.425,-1.825)
  oval 0.787x1.651 smd: 1(0,0) 2(1.4,0) 3(2.8,0) 4(4.2,0) 5(7.1,0) 6(9.9,0) 7(11.3,0) 8(12.7,0) 9(-1.4,0) 18(8.5,0) 19(14.1,0)
  oval 1.346x0.787 smd: 10(-9.2,-22.975) 11(-9.2,-24.075) 12(-9.2,-25.175) 13(-9.2,-26.275) 14(20.05,-26.275) 15(20.05,-25.175) 16(20.05,-24.075) 17(20.05,-22.975)
  rect 1.397x1.448 smd: 20(17.2,0.6) 21(5.65,0.6) 22(-6.35,0.6)
  rect 1.448x1.397 smd: 23(19.525,-6.575) 24(-8.675,-6.575) 25(19.525,-20.675) 26(-8.675,-18.825)
TAIYO_BRC2012T4R7MD_2P
  rect 0.61x1.448 smd: 1(0,0) 2(1.6,0)
TAIYO_FBMJ4516HS720NT_2P
  rect 1.549x1.854 smd: 1(0,0) 2(3.95,0)
TC7SH08FU_SSOP5
  oval 0.406x0.787 smd: 1(0,0) 2(0.65,0) 3(1.3,0) 4(1.3,1.9) 5(0,1.9)
TOKO_FDVE1040-H-3R3M-P3_2P
  rect 3.81x3.988 smd: 1(0,0) 2(9.8,0)
TPC12
  round 0.305 smd: 1(0,0)
TPS2544RTER_WQFN16_3X3
  oval 0.254x0.889 smd: 1(0,0) 2(0.5,0) 3(1,0) 4(1.5,0) 9(1.5,3.1) 10(1,3.1) 11(0.5,3.1) 12(0,3.1)
  oval 0.889x0.254 smd: 5(2.3,0.8) 6(2.3,1.3) 7(2.3,1.8) 8(2.3,2.3) 13(-0.8,2.3) 14(-0.8,1.8) 15(-0.8,1.3) 16(-0.8,0.8)
  rect 1.651x1.651 smd: 17(0.75,1.55)
TPS22965DSGR_SON8_2X2
  oval 0.254x0.787 smd: 1(0,0) 2(0.5,0) 3(1,0) 4(1.5,0) 5(1.5,2.2) 6(1,2.2) 7(0.5,2.2) 8(0,2.2)
  rect 1.6x0.889 smd: 9(0.75,1.1)
TPS22966DPUR_SON14_2X3
  oval 0.203x0.762 smd: 1(0,0) 2(0.4,0) 3(0.8,0) 4(1.2,0) 5(1.6,0) 6(2,0) 7(2.4,0) 8(2.4,2.05) 9(2,2.05) 10(1.6,2.05) 11(1.2,2.05) 12(0.8,2.05) 13(0.4,2.05) 14(0,2.05)
  rect 2.489x0.889 smd: 15(1.2,1.025)
TPS51285BRUKR_QFN20_3X3
  oval 0.203x1.016 smd: 1(0,0) 2(0.4,0) 3(0.8,0) 4(1.2,0) 5(1.6,0) 11(1.6,2.975) 12(1.2,2.975) 13(0.8,2.975) 14(0.4,2.975) 15(0,2.975)
  oval 1.016x0.203 smd: 6(2.288,0.688) 7(2.288,1.088) 8(2.288,1.488) 9(2.288,1.888) 10(2.288,2.288) 16(-0.688,2.288) 17(-0.688,1.888) 18(-0.688,1.488) 19(-0.688,1.088) 20(-0.688,0.688)
  rect 1.702x1.702 smd: 21(0.8,1.488)
TPS51622RSM_QFN32_4X4
  oval 0.203x0.914 smd: 1(0,0) 2(0.4,0) 3(0.8,0) 4(1.2,0) 5(1.6,0) 6(2,0) 7(2.4,0) 8(2.8,0) 17(2.8,4.077) 18(2.4,4.077) 19(2,4.077) 20(1.6,4.077) 21(1.2,4.077) 22(0.8,4.077) 23(0.4,4.077) 24(0,4.077)
  oval 0.914x0.203 smd: 9(3.438,0.639) 10(3.438,1.039) 11(3.438,1.438) 12(3.438,1.838) 13(3.438,2.239) 14(3.438,2.639) 15(3.438,3.039) 16(3.438,3.438) 25(-0.639,3.438) 26(-0.639,3.039) 27(-0.639,2.639) 28(-0.639,2.239) 29(-0.639,1.838) 30(-0.639,1.438) 31(-0.639,1.039) 32(-0.639,0.639)
  rect 2.794x2.794 smd: 33(1.4,2.039)
TVNST52302AB0_SOT523-3
  oval 0.508x0.559 smd: 1(0,0) 2(-0.5,-1.4) 3(0.5,-1.4)
TYCO_2-1775293-2_2P
  oval 0.787x1.6 smd: 1(0,0) 2(-1.25,0)
  rect 2.108x2.997 smd: 3(2.55,2.9) 4(-3.8,2.9)
W25Q32FVSSIQ_SO8
  oval 0.635x1.676 smd: 1(0,0) 2(1.27,0) 3(2.54,0) 4(3.81,0) 5(3.81,7.25) 6(2.54,7.25) 7(1.27,7.25) 8(0,7.25)
W25Q64FVSSIQ_SO8
  oval 0.635x1.676 smd: 1(0,0) 2(1.27,0) 3(2.54,0) 4(3.81,0) 5(3.81,7.25) 6(2.54,7.25) 7(1.27,7.25) 8(0,7.25)
WGI217LM-QPN9-A2_QFN48_6X6
  oval 0.203x1.041 smd: 1(0,0) 2(0.4,0) 3(0.8,0) 4(1.2,0) 5(1.6,0) 6(2,0) 7(2.4,0) 8(2.8,0) 9(3.2,0) 10(3.6,0) 11(4,0) 12(4.4,0) 25(4.4,5.95) 26(4,5.95) 27(3.6,5.95) 28(3.2,5.95) 29(2.8,5.95) 30(2.4,5.95) 31(2,5.95) 32(1.6,5.95) 33(1.2,5.95) 34(0.8,5.95) 35(0.4,5.95) 36(0,5.95)
  oval 1.041x0.203 smd: 13(5.175,0.775) 14(5.175,1.175) 15(5.175,1.575) 16(5.175,1.975) 17(5.175,2.375) 18(5.175,2.775) 19(5.175,3.175) 20(5.175,3.575) 21(5.175,3.975) 22(5.175,4.375) 23(5.175,4.775) 24(5.175,5.175) 37(-0.775,5.175) 38(-0.775,4.775) 39(-0.775,4.375) 40(-0.775,3.975) 41(-0.775,3.575) 42(-0.775,3.175) 43(-0.775,2.775) 44(-0.775,2.375) 45(-0.775,1.975) 46(-0.775,1.575) 47(-0.775,1.175) 48(-0.775,0.775)
  rect 2.997x2.997 smd: 49(2.2,2.975)
Y_7V25000034_4P
  rect 1.397x1.194 smd: 1(0,0) 2(2.2,0) 3(2.2,1.8) 4(0,1.8)
Y_9H03220008_2P
  rect 0.991x1.803 smd: 1(0,0) 2(2.5,0)
Y_Q13FC135000040_2P
  rect 0.991x1.803 smd: 1(0,0) 2(2.5,0)
Y_X3G024000DC1H_4P
  rect 1.397x1.194 smd: 1(0,0) 2(2.2,0) 3(2.2,1.7) 4(0,1.7)

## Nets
0.675V_DDR_VTT_ON: PR210.1 QD1.2 RD9.2 RD14.2 UD1.4
1.05V_M_PWRGD: PR313.1 RC27.1
1.05V_MODPHY_EN: CZ25.1 QZ6.3 QZ10.3 RZ5.2
1.05V_MP_PWROK: PR313.2 PR315.2 PU300.2
1.5VSP: PC403.1 PC404.1 PJP401.1 PR402.1 PU400.3 PU400.4
1.35V_B+: PC200.1 PC201.1 PC203.1 PJP200.2 PQ200.5 PR206.1
1.35V_FB: PC213.1 PR205.1 PR209.1 PU200.6
3.3V_CAM_EN#: QZ1.2 RC174.1 UC1.AM4
3.3V_HDD_EN: RN6.2 RN7.1 UC1.K2 UN3.3
3.3V_TP_EN: RPC3.7 UC1.L5
3.3V_TS_EN: QV7.2 RPC4.7 UC1.N7
+0.9V_LAN: CL3.1 CL4.1 CL8.1 CL9.1 CL10.1 CL11.1 CL12.1 LL1.2 UL1.8 UL1.11 UL1.16 UL1.22 UL1.37 UL1.40 UL1.43 UL1.46 UL1.47
+0.675V_DDR_VTT: CD24.1 CD25.1 CD26.1 CD27.1 CD28.1 CD29.1 CD57.1 CD58.1 CD59.1 CD60.1 CD61.1 CD62.1 JDIMM1.203 JDIMM1.204 JDIMM2.203 JDIMM2.204 PJP202.2
+0.675V_P: PC205.1 PJP202.1 PU200.2 PU200.20
+1.2V_LDO: CR9.2 CR10.2 CR13.2 CR18.2 CR19.2 CR21.2 CR22.2 UR1.1 UR1.10 UR1.28 UR1.31 UR1.36 UR1.41
+1.05V_M: CC39.1 CC61.1 PJP300.2 QZ6.1 QZ6.2 QZ6.5 QZ6.6 RC14.2 RC15.2 RC16.2 RC18.2 RC300.1 RZ44.1 UC1.AE9 UC1.AF9 UC1.AG8 UC1.AG13 UC1.AG14 UZ8.6 UZ8.7
+1.05V_MODPHY: CZ38.1 LC1.1 LC2.1 PJP35.1 PJP36.2 QZ6.4
+1.05V_MODPHY_PCH: CC40.1 CC43.1 CC44.1 PJP35.2 UC1.K9 UC1.L10 UC1.M9
+1.05V_MP: PC304.1 PC305.1 PC306.1 PC307.1 PC308.1 PJP300.1 PL301.2 PR307.1
+1.05V_RUN: CC41.1 CC42.1 CC58.1 CC59.1 CC60.1 CC70.1 CC71.1 CC72.1 CC79.1 CC84.1 CC85.1 CE25.1 JXDP1.43 JXDP1.44 LC3.1 LC4.1 LC5.1 PJP18.2 PJP23.1 PJP36.1 RC117.1 RC124.1 RC125.1 RC126.1 RC127.1 RC196.2 RC197.1 RE70.1 RZ44.2 UC1.AE8 UC1.AF22 UC1.AG16 UC1.AG17 UC1.H11 UC1.H15 UC1.J11 UC1.J17 UC1.N8 UC1.P9 UC1.R21 UC1.T21 UE2.B51
+1.5V_RUN: PJP401.2 RA3.1 UC1.J15
+1.5V_RUN_AUDIO: CA16.1 RA3.2 UA1.40
+1.05V_RUN_UZ8: CZ39.2 PJP18.1 UZ8.8 UZ8.9
+1.05V_VCCST: CC36.1 CC37.1 PC511.1 PJP23.2 PR527.1 PR528.1 PR529.1 RC25.1 RC114.1 RC116.1 RC199.1 RC202.2 RC204.1 RC208.1 UC1.AC22 UC1.AE22 UC1.AE23
+1.5V_VIN: PC401.1 PJP400.2 PU400.5 PU400.9
+1.8V_RUN_CARD: CR34.1 JSD1.14 UR1.24
+1.35V_MEM: CC23.2 CC25.1 CC26.1 CC27.1 CC28.1 CC29.1 CC30.1 CC31.1 CC32.1 CC33.1 CC34.1 CD2.1 CD3.1 CD4.1 CD7.1 CD8.1 CD9.1 CD10.1 CD11.1 CD12.1 CD13.1 CD14.1 CD15.1 CD16.1 CD17.1 CD18.1 CD19.1 CD20.1 CD30.1 CD37.1 CD38.1 CD39.1 CD40.1 CD41.1 CD42.1 CD43.1 CD44.1 CD45.1 CD46.1 CD47.1 CD48.1 CD49.1 CD50.1 CD51.1 CD52.1 CD53.1 JDIMM1.75 JDIMM1.76 JDIMM1.81 JDIMM1.82 JDIMM1.87 JDIMM1.88 JDIMM1.93 JDIMM1.94 JDIMM1.99 JDIMM1.100 JDIMM1.105 JDIMM1.106 JDIMM1.111 JDIMM1.112 JDIMM1.117 JDIMM1.118 JDIMM1.123 JDIMM1.124 JDIMM2.75 JDIMM2.76 JDIMM2.81 JDIMM2.82 JDIMM2.87 JDIMM2.88 JDIMM2.93 JDIMM2.94 JDIMM2.99 JDIMM2.100 JDIMM2.105 JDIMM2.106 JDIMM2.111 JDIMM2.112 JDIMM2.117 JDIMM2.118 JDIMM2.123 JDIMM2.124 PJP203.2 PJP204.2 QD1.1 RD2.1 RD4.1 RD18.1 RD22.1 UC1.AH26 UC1.AJ31 UC1.AJ33 UC1.AJ37 UC1.AN33 UC1.AP43 UC1.AR48 UC1.AY35 UC1.AY40 UC1.AY44 UC1.AY50 UD1.5
+1.35V_MEN_P: PC207.1 PC213.2 PC214.1 PJP201.2 PJP203.1 PJP204.1 PL200.1 PR205.2 PU200.5
+3.3V_ALW: CC35.1 CE1.1 CE21.1 CV10.1 CZ34.1 CZ48.1 JKBTP1.11 JLED1.8 PC310.1 PJP14.1 PJP15.1 PJP102.2 PR2.1 PR8.2 PR107.1 PR306.1 PR315.1 PU300.7 RC213.1 RC217.1 RE8.1 RE11.1 RE25.1 RE35.1 RE36.1 RE37.1 RE43.1 RE63.1 RE68.1 RE69.1 RE71.1 RE72.1 RE73.1 RE75.1 RE79.1 RE81.1 RE83.1 RE84.2 RPE3.7 RPE3.8 RPE5.8 RPE6.6 RPE6.7 RPE6.8 RPE7.5 RPE7.6 RPE7.7 RPE7.8 RPE9.5 RPE9.6 RPE9.7 RPE9.8 RZ22.1 RZ24.1 RZ31.1 UC8.5 UV24.4 UV24.5 UZ2.1 UZ2.2 UZ2.6 UZ2.7 UZ3.1 UZ3.2 UZ6.5 UZ8.1 UZ8.2 UZ9.1 UZ9.2 UZ10.5 UZ11.5
+3.3V_ALW2: PC100.2 PR103.2 PU100.3 RE57.2 RZ16.1 UC6.5
+3.3V_ALW_DEG: JDEG1.1 RE71.2
+3.3V_ALW_PCH: CC57.1 CC63.1 JAPS1.1 PJP20.2 RC2.1 RC33.1 RC34.1 RC79.1 RC81.1 RC82.1 RC120.2 RC179.1 RC212.1 RC216.1 RC245.2 RPC5.1 RPC5.2 RPC5.3 RPC5.4 RPC7.1 RPC7.2 RPC7.3 RPC7.4 RPC10.1 RPC10.2 RPC10.3 RPC10.4 RPC14.5 RPC14.6 RPC14.7 RPC14.8 RPC19.5 RPC19.6 RPC19.7 RPC19.8 UC1.AA9 UC1.AC9 UC1.AE20 UC1.AE21 UC1.AH14
+3.3V_ALW_PCH_UZ2: CZ43.1 PJP20.1 UZ2.13 UZ2.14
+3.3V_ALW_UE2: CE13.1 CE14.1 CE15.1 CE16.1 CE17.1 CE18.1 CE19.1 CE20.1 CE22.1 CE23.1 PJP15.2 UE2.A11 UE2.A22 UE2.A26 UE2.A41 UE2.A52 UE2.A58 UE2.B3 UE2.B35
+3.3V_ALW_UE3: CE2.1 CE3.1 PJP14.2 UE3.8 UE3.28
+3.3V_ALWP: PC113.1 PJP102.1 PL101.1 PR100.1
+3.3V_CAM: CZ1.1 JEDP1.11 QZ1.1
+3.3V_HDD: CN15.1 CN16.1 CN24.1 CN29.1 JSATA1.9 JSATA1.10 PJP4.2 PJP7.2 RN5.1 RN8.2 RN10.2 RN12.2 RN14.1 RN18.1 RN20.1 RN22.1 RN24.1 UN2.10 UN2.20
+3.3V_LAN: CL15.1 CL18.1 CL19.1 JLOM1.9 JLOM1.12 PJP13.2 RL1.1 RL2.1 RL4.2 RL5.1 RL6.1 RL8.1 RL29.1 RL30.1 UL2.5
+3.3V_LAN_OUT: CL7.1 RL8.2 UL1.4 UL1.5 UL1.15 UL1.19 UL1.29
+3.3V_LAN_UZ2: CZ50.1 PJP13.1 UZ2.8 UZ2.9
+3.3V_M: JSPI1.16 PJP11.1 PJP19.2 RC231.1 RZ46.2 UC1.Y8
+3.3V_M_TPM: CZ4.1 CZ5.1 CZ6.1 CZ7.1 PJP11.2 UZ1.3 UZ1.10 UZ1.19 UZ1.24
+3.3V_M_UZ8: CZ40.2 PJP19.1 UZ8.13 UZ8.14
+3.3V_MMI: CR1.1 CR2.1 CR3.1 CR4.1 CR6.1 CR7.2 CR8.2 PJP26.2 RR6.1 RR15.1 UR1.9 UR1.11 UR1.13 UR1.23 UR1.27 UR1.42
+3.3V_RTC_LDO: PD3.3 PR103.1
+3.3V_RUN: CC17.1 CC64.1 CC66.1 CC69.1 CC85.2 CC96.2 CD31.1 CD32.1 CD63.1 CD64.1 CN1.1 CN2.1 CV61.1 CV62.1 CV66.1 CV69.1 CV510.1 CV514.1 JDIMM1.199 JDIMM2.199 JEDP1.10 JLPDE1.1 JLPDE1.2 MIC1.6 PJP4.1 PJP10.1 PJP16.1 PJP21.1 PJP26.1 PJP400.1 PR400.1 PR516.2 PR519.2 PU500.20 PU500.21 QC1.2 QC1.5 QV8.3 QZ1.3 RC66.1 RC68.1 RC95.1 RC122.1 RC155.2 RC156.2 RC158.1 RC160.1 RC163.1 RC164.1 RC176.1 RC180.1 RC247.2 RC302.1 RD27.2 RE48.1 RE51.1 RE67.1 RN2.1 RN3.1 RN4.1 RN6.1 RPC2.5 RPC2.6 RPC2.7 RPC2.8 RPC3.1 RPC3.2 RPC3.3 RPC3.4 RPC4.1 RPC4.2 RPC4.3 RPC4.4 RPC6.1 RPC6.3 RPC6.4 RPC8.1 RPC8.2 RPC8.3 RPC8.4 RPC9.2 RPC9.3 RPC9.4 RPC15.5 RPC15.6 RPC15.7 RPC15.8 RPC16.1 RPC16.2 RPC16.3 RPC16.4 RPC17.1 RPC17.2 RPC17.3 RPC17.4 RPC18.1 RPC18.2 RPC18.3 RPC18.4 RPC20.5 RPC20.8 RPE3.5 RPE3.6 RV6.1 RV8.1 RV51.1 RV54.1 RV55.1 RV56.1 RV57.1 RV58.1 RV60.1 RV68.1 RV501.1 RV507.1 RV511.1 RV515.1 RZ8.1 RZ9.1 RZ46.1 UC1.K14 UC1.K16 UC1.T9 UC1.U8 UC1.V8 UC1.W9 UC4.5 UC5.5 UC7.14 UN1.1 UN1.7 UN1.8 UN1.14 UN3.1 UN3.2 UV7.14 UV7.28 UV7.41 UV7.56 UV501.1 UV502.14
+3.3V_RUN_AUDIO: CA10.1 CA11.1 CA50.1 PJP10.2 RA1.1 RA4.1 RA18.1 RA45.2 UA1.3 UA1.9
+3.3V_RUN_CARD: CR31.1 JSD1.4 UR1.22
+3.3V_RUN_UN3: CN3.2 PJP7.1 UN3.7 UN3.8
+3.3V_RUN_UZ9: CZ44.1 PJP21.2 UZ9.13 UZ9.14
+3.3V_SPI: CC6.1 CC7.1 JSPI1.15 RC29.1 RC31.1 RC231.2 UC2.8 UC3.8
+3.3V_TP: JKBTP1.5 PJP16.2 RZ18.1 RZ19.1
+3.3V_TSP: CZ2.1 JEDP1.1 QV8.1
+3.3V_WLAN: CZ15.1 CZ16.1 CZ17.2 CZ18.2 CZ19.1 CZ20.1 JNGFF1.2 JNGFF1.4 JNGFF1.64 JNGFF1.66 PJP12.1 QZ2.2 QZ2.5 RZ14.2 RZ15.2
+3.3V_WLAN_UZ3: CZ36.1 PJP12.2 UZ3.7 UZ3.8
+3V5V_PWR_SRC: PC101.1 PC102.1 PC105.1 PC117.1 PJP100.2 PL100.2 PQ100.5 PQ101.5 PU100.12
+5V_ALW: CC95.2 CI6.1 CI7.1 CI11.1 CI12.1 CI19.1 JLED1.1 LED3.2 PC20.1 PC400.1 PJP101.2 PR11.1 PR202.1 PR204.2 PR526.1 PU400.6 RD9.1 RI13.2 RZ5.1 RZ21.1 UI1.2 UI1.3 UI2.2 UI2.3 UI3.1 UI3.7 UI3.8 UN3.4 UZ2.4 UZ3.4 UZ8.4 UZ9.4 UZ9.6 UZ9.7
+5V_ALW2: PC118.1 PU100.13
+5V_ALW_UZ5: CZ35.1 RZ21.2 UZ5.1
+5V_ALWP: PC115.1 PJP101.1 PL102.2 PR101.2 PU100.14
+5V_HDD: CN13.1 CN14.1 JSATA1.15 JSATA1.16 JSATA1.17 PJP5.2 RN1.1
+5V_RUN: CE32.1 CV23.1 DE1.1 JFAN1.4 JKBTP1.12 PC509.1 PJP5.1 PJP9.1 PJP22.2 PU501.2 QV501.2 UV2.1
+5V_RUN_AUDIO: LA5.2 PJP9.2 RA39.1
+5V_RUN_PVDD: CA45.1 CA46.1 CA47.1 CA48.1 RA39.2 UA1.41 UA1.46
+5V_RUN_UZ9: CZ47.1 PJP22.1 UZ9.8 UZ9.9
+5V_USB_CHG_PWR: CI14.1 CI17.1 JUSB3.1 UI3.12
+GND_CHASSIS: CL22.2 RL15.2 RL16.2 RL17.2 RL18.2
+V1.05S_APLLOPI: CC67.1 CC68.1 LC3.2 UC1.AA21 UC1.W21
+V1.05SP_B+: PC300.1 PC303.1 PJP302.2 PU300.8
+VCC_CORE: CC23.1 CC79.2 CC84.2 PC900.1 PC901.1 PC902.1 PC903.1 PC904.1 PC913.1 PC914.1 PC915.1 PC916.1 PC917.1 PC966.1 PL500.1 RC209.1 UC1.AB57 UC1.AD57 UC1.AG57 UC1.C24 UC1.C28 UC1.C32 UC1.C36 UC1.C40 UC1.C44 UC1.C48 UC1.C52 UC1.C56 UC1.E23 UC1.E25 UC1.E27 UC1.E29 UC1.E31 UC1.E33 UC1.E35 UC1.E37 UC1.E39 UC1.E41 UC1.E43 UC1.E45 UC1.E47 UC1.E49 UC1.E51 UC1.E53 UC1.E55 UC1.E57 UC1.F24 UC1.F28 UC1.F32 UC1.F36 UC1.F40 UC1.F44 UC1.F48 UC1.F52 UC1.F56 UC1.F59 UC1.G23 UC1.G25 UC1.G27 UC1.G29 UC1.G31 UC1.G33 UC1.G35 UC1.G37 UC1.G39 UC1.G41 UC1.G43 UC1.G45 UC1.G47 UC1.G49 UC1.G51 UC1.G53 UC1.G55 UC1.G57 UC1.H23 UC1.J23 UC1.K23 UC1.K57 UC1.L22 UC1.M23 UC1.M57 UC1.P57 UC1.U57 UC1.W57
+VCC_PWR_SRC: PC503.2 PC515.1 PC516.1 PC517.1 PC518.1 PC519.1 PC520.1 PJP500.2 PL501.2 PR511.1 PR518.1 PU501.5
+VCCIO_OUT: RC196.1 UC1.A59
+VCCIOA_OUT: RC133.1 UC1.E20
+VDDA_AVDD1: CA8.1 CA9.1 LA5.1 UA1.27
+VDDA_PVDD: CA17.1 CA18.1 RA4.2 UA1.38
GND: CA5.2 CA6.2 CA10.2 CA11.2 CA12.2 CA13.2 CA19.2 CA22.2 CA23.2 CA24.2 CA30.2 CA31.2 CA33.2 CA45.2 CA46.2 CA47.2 CA48.2 CA49.1 CA50.2 CA53.2 CA54.2 CC1.1 CC2.1 CC3.1 CC4.1 CC5.2 CC6.2 CC7.2 CC8.1 CC9.1 CC10.1 CC11.1 CC12.1 CC13.1 CC17.2 CC20.2 CC21.2 CC22.2 CC24.2 CC25.2 CC26.2 CC27.2 CC28.2 CC29.2 CC30.2 CC31.2 CC32.2 CC33.2 CC34.2 CC35.2 CC36.2 CC37.2 CC39.2 CC40.2 CC41.2 CC42.2 CC43.2 CC44.2 CC47.2 CC49.2 CC50.2 CC51.2 CC52.2 CC55.2 CC56.2 CC57.2 CC58.2 CC59.2 CC60.2 CC61.2 CC63.2 CC64.2 CC65.2 CC66.2 CC67.2 CC68.2 CC69.2 CC70.2 CC71.2 CC72.2 CC73.2 CC77.2 CC78.2 CC80.2 CC81.2 CC82.2 CC83.2 CC96.1 CC100.1 CD1.2 CD2.2 CD3.2 CD4.2 CD5.2 CD6.2 CD7.2 CD8.2 CD9.2 CD10.2 CD11.2 CD12.2 CD13.2 CD14.2 CD15.2 CD16.2 CD17.2 CD18.2 CD19.2 CD20.2 CD22.2 CD23.2 CD24.2 CD25.2 CD26.2 CD27.2 CD28.2 CD29.2 CD30.2 CD31.2 CD32.2 CD33.2 CD34.2 CD35.2 CD37.2 CD38.2 CD39.2 CD40.2 CD41.2 CD42.2 CD43.2 CD44.2 CD45.2 CD46.2 CD47.2 CD48.2 CD49.2 CD50.2 CD51.2 CD52.2 CD53.2 CD55.2 CD56.2 CD57.2 CD58.2 CD59.2 CD60.2 CD61.2 CD62.2 CD63.2 CD64.2 CE1.2 CE2.2 CE3.2 CE8.2 CE10.2 CE11.2 CE12.2 CE13.2 CE14.2 CE15.2 CE16.2 CE17.2 CE18.2 CE19.2 CE20.2 CE21.2 CE22.2 CE23.2 CE25.2 CE28.2 CE29.2 CE30.2 CE31.2 CE32.2 CE34.2 CE36.2 CE38.2 CE40.2 CI1.2 CI3.2 CI6.2 CI7.2 CI8.2 CI10.2 CI11.2 CI12.2 CI14.2 CI17.2 CI19.2 CL3.2 CL4.2 CL7.2 CL8.2 CL9.2 CL10.2 CL11.2 CL12.2 CL13.1 CL14.1 CL15.2 CL16.2 CL17.2 CL18.2 CL19.2 CL20.2 CL21.2 CL22.1 CMOS1.1 CN1.2 CN2.2 CN3.1 CN4.2 CN13.2 CN14.2 CN15.2 CN16.2 CN24.2 CN29.2 CR1.2 CR2.2 CR3.2 CR4.2 CR6.2 CR7.1 CR8.1 CR9.1 CR10.1 CR13.1 CR14.1 CR15.1 CR17.1 CR18.1 CR19.1 CR21.1 CR22.1 CR23.2 CR31.2 CR34.2 CR35.2 CV9.2 CV10.2 CV12.2 CV23.2 CV26.2 CV27.2 CV60.2 CV61.2 CV62.2 CV66.2 CV69.2 CV509.2 CV510.2 CV514.2 CZ1.2 CZ2.2 CZ4.2 CZ5.2 CZ6.2 CZ7.2 CZ9.2 CZ15.2 CZ16.2 CZ17.1 CZ18.1 CZ19.2 CZ20.2 CZ23.2 CZ25.2 CZ30.2 CZ31.2 CZ34.2 CZ35.2 CZ36.2 CZ37.2 CZ38.2 CZ39.1 CZ40.1 CZ41.2 CZ42.2 CZ43.2 CZ44.2 CZ45.2 CZ46.2 CZ47.2 CZ48.2 CZ50.2 CZ64.2 DA1.1 DA2.1 DA3.1 DA6.1 DA7.1 DE1.2 DI1.3 DI2.1 DI3.1 DI4.3 DI5.1 DI6.3 DV4.1 H1.1(TP-1) H2.1(TP-1) H3.1(TP-1) H4.1(TP-1) H6.1(TP-1) H7.1(TP-1) H9.1(TP-1) H10.1(TP-1) H11.1(TP-1) H12.1(TP-1) H13.1(TP-1) H14.1(TP-1) H15.1(TP-1) H16.1(TP-1) H17.1(TP-1) H19.1(TP-1) H21.1(TP-1) H22.1(TP-1) JAPS1.8 JAPS1.10 JAPS1.12 JAPS1.14 JAPS1.19 JAPS1.20 JDEG1.10 JDEG1.11 JDEG1.12 JDIMM1.2 JDIMM1.3 JDIMM1.8 JDIMM1.9 JDIMM1.11 JDIMM1.13 JDIMM1.14 JDIMM1.19 JDIMM1.20 JDIMM1.25 JDIMM1.26 JDIMM1.28 JDIMM1.31 JDIMM1.32 JDIMM1.37 JDIMM1.38 JDIMM1.43 JDIMM1.44 JDIMM1.46 JDIMM1.48 JDIMM1.49 JDIMM1.54 JDIMM1.55 JDIMM1.60 JDIMM1.61 JDIMM1.63 JDIMM1.65 JDIMM1.66 JDIMM1.71 JDIMM1.72 JDIMM1.127 JDIMM1.128 JDIMM1.133 JDIMM1.134 JDIMM1.136 JDIMM1.138 JDIMM1.139 JDIMM1.144 JDIMM1.145 JDIMM1.150 JDIMM1.151 JDIMM1.153 JDIMM1.155 JDIMM1.156 JDIMM1.161 JDIMM1.162 JDIMM1.167 JDIMM1.168 JDIMM1.170 JDIMM1.172 JDIMM1.173 JDIMM1.178 JDIMM1.179 JDIMM1.184 JDIMM1.185 JDIMM1.187 JDIMM1.189 JDIMM1.190 JDIMM1.195 JDIMM1.196 JDIMM2.2 JDIMM2.3 JDIMM2.8 JDIMM2.9 JDIMM2.11 JDIMM2.13 JDIMM2.14 JDIMM2.19 JDIMM2.20 JDIMM2.25 JDIMM2.26 JDIMM2.28 JDIMM2.31 JDIMM2.32 JDIMM2.37 JDIMM2.38 JDIMM2.43 JDIMM2.44 JDIMM2.46 JDIMM2.48 JDIMM2.49 JDIMM2.54 JDIMM2.55 JDIMM2.60 JDIMM2.61 JDIMM2.63 JDIMM2.65 JDIMM2.66 JDIMM2.71 JDIMM2.72 JDIMM2.127 JDIMM2.128 JDIMM2.133 JDIMM2.134 JDIMM2.136 JDIMM2.138 JDIMM2.139 JDIMM2.144 JDIMM2.145 JDIMM2.150 JDIMM2.151 JDIMM2.153 JDIMM2.155 JDIMM2.156 JDIMM2.161 JDIMM2.162 JDIMM2.167 JDIMM2.168 JDIMM2.170 JDIMM2.172 JDIMM2.173 JDIMM2.178 JDIMM2.179 JDIMM2.184 JDIMM2.185 JDIMM2.187 JDIMM2.189 JDIMM2.190 JDIMM2.195 JDIMM2.196 JEDP1.4 JEDP1.6 JEDP1.8 JEDP1.15 JEDP1.23 JEDP1.24 JEDP1.25 JEDP1.27 JEDP1.28 JEDP1.39 JEDP1.41 JEDP1.42 JEDP1.43 JEDP1.44 JEDP1.45 JFAN1.1 JFAN1.5 JFAN1.6 JHDMI1.2 JHDMI1.5 JHDMI1.8 JHDMI1.11 JHDMI1.17 JHDMI1.20 JHDMI1.21 JHDMI1.22 JHDMI1.23 JKBTP1.1 JKBTP1.2 JKBTP1.8 JKBTP1.14 JKBTP1.15 JKBTP1.17 JKBTP1.18 JLED1.10 JLED1.11 JLED1.12 JLOM1.16 JLOM1.17 JLPDE1.9 JLPDE1.11 JLPDE1.12 JMDP1.1 JMDP1.7 JMDP1.8 JMDP1.13 JMDP1.14 JMDP1.19 JMDP1.21 JMDP1.22 JMDP1.23 JMDP1.24 JNGFF1.1 JNGFF1.7 JNGFF1.10 JNGFF1.15 JNGFF1.16 JNGFF1.21 JNGFF1.22 JNGFF1.25 JNGFF1.28 JNGFF1.31 JNGFF1.37 JNGFF1.43 JNGFF1.49 JNGFF1.55 JNGFF1.61 JNGFF1.67 JNGFF1.68 JNGFF1.69 JRTC1.2 JRTC1.3 JRTC1.4 JSATA1.1 JSATA1.4 JSATA1.7 JSATA1.12 JSATA1.14 JSATA1.18 JSATA1.21 JSATA1.22 JSATA1.23 JSATA1.24 JSD1.3 JSD1.6 JSD1.10 JSD1.13 JSD1.17 JSD1.20 JSD1.21 JSD1.22 JSD1.23 JSD1.24 JSD1.25 JSD1.26 JSPI1.18 JSPI1.19 JSPI1.20 JSPI1.21 JSPI1.22 JSPI1.23 JSPI1.24 JSPK1.5 JSPK1.6 JTAG1.2 JUSB1.4 JUSB1.7 JUSB1.10 JUSB1.11 JUSB1.12 JUSB1.13 JUSB2.4 JUSB2.7 JUSB2.10 JUSB2.11 JUSB2.12 JUSB2.13 JUSB3.4 JUSB3.7 JUSB3.10 JUSB3.11 JUSB3.12 JUSB3.13 JXDP1.1 JXDP1.2 JXDP1.7 JXDP1.8 JXDP1.13 JXDP1.14 JXDP1.19 JXDP1.20 JXDP1.25 JXDP1.26 JXDP1.31 JXDP1.32 JXDP1.37 JXDP1.38 JXDP1.49 JXDP1.50 JXDP1.59 MIC1.1 MIC1.2 MIC1.3 PBATT1.7 PBATT1.8 PBATT1.9 PBATT1.10 PC1.2 PC3.2 PC9.2 PC20.2 PC21.2 PC22.2 PC100.1 PC101.2 PC102.2 PC105.2 PC111.2 PC113.2 PC114.2 PC115.2 PC117.2 PC118.2 PC119.2 PC200.2 PC201.2 PC203.2 PC205.2 PC207.2 PC208.2 PC209.1 PC211.2 PC212.2 PC214.2 PC215.2 PC300.2 PC301.2 PC303.2 PC305.2 PC306.2 PC307.2 PC308.2 PC309.2 PC310.2 PC400.2 PC401.2 PC402.2 PC404.2 PC500.2 PC501.2 PC503.1 PC505.2 PC507.2 PC508.2 PC509.2 PC510.2 PC511.2 PC514.2 PC515.2 PC516.2 PC517.2 PC518.2 PC519.2 PC520.2 PC704.2 PC705.2 PC706.2 PC707.2 PC708.2 PC709.2 PC710.2 PC713.2 PC714.2 PC715.2 PC716.2 PC717.2 PC721.2 PC722.2 PC723.2 PC724.2 PC725.2 PC734.2 PC900.2 PC901.2 PC902.2 PC903.2 PC904.2 PC913.2 PC914.2 PC915.2 PC916.2 PC917.2 PC966.2 PD1.1 PD2.1 PD5.1 PJP1.2 PJP6.2 PJP701.2 PQ3.3 PQ102.1 PQ102.2 PQ102.3 PQ103.1 PQ103.2 PQ103.3 PQ201.1 PQ201.2 PQ201.3 PQ705.3 PQ705.4 PQ705.5 PQ708.6 PR12.1 PR16.2 PR102.1 PR104.2 PR105.1 PR106.1 PR114.2 PR209.2 PR303.2 PR308.2 PR310.2 PR401.2 PR403.2 PR505.2 PR506.2 PR507.2 PR508.2 PR509.2 PR510.2 PR513.2 PR525.2 PR709.2 PU100.21 PU200.1 PU200.3 PU200.14 PU200.21 PU300.9 PU400.1 PU500.19 PU500.22 PU500.29 PU500.33 PU501.3 PU501.9 PU700.22 QA1.3 QE2.1 QE2.4 QN1.1 QN1.4 QV2.3 QV7.3 QV502.3 QZ10.1 QZ10.4 RA2.2 RA35.2 RA36.2 RA37.2 RC21.2 RC80.2 RC91.1 RC123.2 RC128.1 RC129.1 RC130.2 RC131.2 RC132.2 RC139.1 RC140.2 RC141.1 RC142.1 RC152.2 RC171.2 RC174.2 RC175.2 RC178.2 RC183.2 RC184.2 RC185.2 RC186.1 RC187.2 RC188.2 RC189.2 RC190.2 RC191.2 RC198.2 RC218.2 RC240.2 RC241.2 RC242.2 RC243.2 RC303.2 RC304.2 RC305.2 RC306.2 RD6.2 RD7.2 RD14.1 RD15.1 RD16.1 RD20.2 RD21.2 RD24.2 RD25.2 RD28.2 RE20.1 RE21.1 RE24.2 RE55.1 RE56.1 RE58.2 RE65.2 RE77.2 RE78.2 RE82.1 RE86.1 RE87.1 RE88.2 RI14.1 RL3.1 RL9.2 RL12.2 RL13.2 RN7.2 RN9.1 RN11.1 RN13.1 RN16.1 RN19.1 RN21.1 RN23.1 RN25.1 RPC6.2 RPC9.1 RPC20.6 RPC20.7 RPE10.5 RPE10.6 RPE10.7 RPE10.8 RR2.1 RR5.2 RR8.2 RR11.2 RV1.2 RV2.2 RV3.1 RV50.2 RV52.2 RV61.2 RV62.2 RV63.2 RV64.2 RV65.2 RV66.2 RV67.1 RV502.1 RV503.1 RV504.2 RV505.1 RV510.2 RV514.1 RZ10.1 RZ27.2 RZ33.2 RZ38.1 SW1.4 SW1.5 SW3.1 SW3.3 UA1.49 UC1.A11 UC1.A14 UC1.A18 UC1.A24 UC1.A28 UC1.A32 UC1.A36 UC1.A40 UC1.A44 UC1.A48 UC1.A52 UC1.A56 UC1.AA1 UC1.AA58 UC1.AB7 UC1.AB10 UC1.AB20 UC1.AB22 UC1.AC61 UC1.AD3 UC1.AD21 UC1.AD63 UC1.AE5 UC1.AE10 UC1.AE58 UC1.AF11 UC1.AF12 UC1.AF14 UC1.AF15 UC1.AF17 UC1.AF18 UC1.AG1 UC1.AG11 UC1.AG21 UC1.AG23 UC1.AG60 UC1.AG61 UC1.AG62 UC1.AG63 UC1.AH16 UC1.AH17 UC1.AH19 UC1.AH20 UC1.AH22 UC1.AH24 UC1.AH28 UC1.AH30 UC1.AH32 UC1.AH34 UC1.AH36 UC1.AH38 UC1.AH40 UC1.AH42 UC1.AH44 UC1.AH46 UC1.AH49 UC1.AH51 UC1.AH53 UC1.AH55 UC1.AH57 UC1.AJ13 UC1.AJ14 UC1.AJ23 UC1.AJ25 UC1.AJ27 UC1.AJ29 UC1.AJ35 UC1.AJ39 UC1.AJ41 UC1.AJ43 UC1.AJ45 UC1.AJ47 UC1.AJ50 UC1.AJ52 UC1.AJ54 UC1.AJ56 UC1.AJ58 UC1.AJ60 UC1.AJ63 UC1.AK3 UC1.AK23 UC1.AK52 UC1.AL10 UC1.AL13 UC1.AL17 UC1.AL20 UC1.AL22 UC1.AL23 UC1.AL26 UC1.AL29 UC1.AL31 UC1.AL33 UC1.AL36 UC1.AL39 UC1.AL40 UC1.AL45 UC1.AL46 UC1.AL51 UC1.AL52 UC1.AL54 UC1.AL57 UC1.AL60 UC1.AL61 UC1.AM1 UC1.AM17 UC1.AM23 UC1.AM31 UC1.AM52 UC1.AN7 UC1.AN17 UC1.AN23 UC1.AN31 UC1.AN32 UC1.AN35 UC1.AN36 UC1.AN39 UC1.AN40 UC1.AN42 UC1.AN43 UC1.AN45 UC1.AN46 UC1.AN48 UC1.AN49 UC1.AN51 UC1.AN52 UC1.AN60 UC1.AN63 UC1.AP3 UC1.AP10 UC1.AP17 UC1.AP20 UC1.AP22 UC1.AP23 UC1.AP26 UC1.AP29 UC1.AP31 UC1.AP38 UC1.AP39 UC1.AP48 UC1.AP52 UC1.AP54 UC1.AP57 UC1.AR5 UC1.AR11 UC1.AR15 UC1.AR17 UC1.AR23 UC1.AR31 UC1.AR33 UC1.AR39 UC1.AR43 UC1.AR49 UC1.AR52 UC1.AT13 UC1.AT35 UC1.AT37 UC1.AT40 UC1.AT42 UC1.AT43 UC1.AT46 UC1.AT49 UC1.AT61 UC1.AT62 UC1.AT63 UC1.AU1 UC1.AU16 UC1.AU18 UC1.AU20 UC1.AU22 UC1.AU24 UC1.AU26 UC1.AU28 UC1.AU30 UC1.AU33 UC1.AU51 UC1.AU53 UC1.AU55 UC1.AU57 UC1.AU59 UC1.AV8 UC1.AV14 UC1.AV16 UC1.AV20 UC1.AV24 UC1.AV28 UC1.AV33 UC1.AV34 UC1.AV36 UC1.AV39 UC1.AV41 UC1.AV43 UC1.AV46 UC1.AV49 UC1.AV51 UC1.AV55 UC1.AV59 UC1.AW4 UC1.AW16 UC1.AW24 UC1.AW33 UC1.AW35 UC1.AW37 UC1.AW40 UC1.AW42 UC1.AW44 UC1.AW47 UC1.AW50 UC1.AW51 UC1.AW59 UC1.AW60 UC1.AY4 UC1.AY6 UC1.AY11 UC1.AY16 UC1.AY18 UC1.AY22 UC1.AY24 UC1.AY26 UC1.AY30 UC1.AY33 UC1.AY51 UC1.AY53 UC1.AY57 UC1.AY59 UC1.B4 UC1.B20 UC1.B24 UC1.B26 UC1.B28 UC1.B32 UC1.B36 UC1.B40 UC1.B44 UC1.B48 UC1.B52 UC1.B56 UC1.B60 UC1.C11 UC1.C14 UC1.C18 UC1.C20 UC1.C25 UC1.C27 UC1.C38 UC1.C39 UC1.C57 UC1.D2 UC1.D5 UC1.D8 UC1.D12 UC1.D14 UC1.D18 UC1.D21 UC1.D23 UC1.D25 UC1.D26 UC1.D27 UC1.D29 UC1.D30 UC1.D31 UC1.D33 UC1.D34 UC1.D35 UC1.D37 UC1.D38 UC1.D39 UC1.D41 UC1.D42 UC1.D43 UC1.D45 UC1.D46 UC1.D47 UC1.D49 UC1.D50 UC1.D51 UC1.D53 UC1.D54 UC1.D55 UC1.D57 UC1.D59 UC1.D62 UC1.D63 UC1.E11 UC1.E17 UC1.F20 UC1.F26 UC1.F30 UC1.F34 UC1.F38 UC1.F42 UC1.F46 UC1.F50 UC1.F54 UC1.F58 UC1.F61 UC1.G3 UC1.G5 UC1.G6 UC1.G8 UC1.G18 UC1.G22 UC1.H13 UC1.H17 UC1.H57 UC1.J10 UC1.J22 UC1.J59 UC1.J63 UC1.K1 UC1.K12 UC1.L7 UC1.L13 UC1.L15 UC1.L17 UC1.L18 UC1.L20 UC1.L58 UC1.L61 UC1.M22 UC1.N3 UC1.N10 UC1.N21 UC1.P22 UC1.P59 UC1.P62 UC1.P63 UC1.R8 UC1.R10 UC1.R22 UC1.T1 UC1.T58 UC1.U9 UC1.U20 UC1.U22 UC1.U61 UC1.V3 UC1.V7 UC1.V10 UC1.V23 UC1.V58 UC1.W20 UC1.W22 UC1.Y10 UC1.Y59 UC1.Y63 UC2.4 UC3.4 UC4.3 UC5.3 UC6.3 UC7.7 UC7.15 UC8.3 UD1.3 UE2.B11 UE2.B18 UE2.B54 UE2.B60 UE2.B66 UE2.C1 UE3.41 UI1.1 UI2.1 UI3.14 UI3.17 UL1.49 UL2.3 UN1.5 UN1.10 UN1.12 UN1.13 UN1.15 UN1.16 UN2.3 UN2.21 UN3.5 UN3.9 UR1.49 UV2.2 UV7.26 UV7.35 UV7.38 UV7.43 UV7.57 UV24.2 UV501.2 UV502.7 UZ1.4 UZ1.8 UZ1.11 UZ1.18 UZ1.25 UZ2.11 UZ2.15 UZ3.5 UZ3.9 UZ5.2 UZ6.3 UZ8.11 UZ8.15 UZ9.11 UZ9.15 UZ10.3 UZ11.3 YL1.2 YL1.4
GNDA: CA1.2 CA2.2 CA3.2 CA4.2 CA8.2 CA9.2 CA16.2 CA17.2 CA18.2 CA25.2 CA26.2 CA35.1 CA41.2 CA51.2 CA52.2 JHP1.7 PJP6.1 QA2.1 QA2.4 RA35.1 RA36.1 RA37.1 RA44.2 UA1.26 UA1.37
GNDA_CHG: PC701.1 PC703.2 PC711.2 PC718.1 PC719.1 PC726.1 PC728.2 PC729.1 PJP701.1 PQ711.3 PR711.2 PR715.2 PR729.2 PR788.1 PU700.29
VCCSENSE: PR531.1 RC209.2 UC1.E63
VDD_1.35V: PC211.1 PR201.1 PR202.2 PU200.11
VSSSENSE: PR532.1 RC218.1 UC1.E62
+AUX_LDO: CR17.2 UR1.12
+BL_PWR_SRC: CV12.1 JEDP1.17 JEDP1.18 JEDP1.19 QV1.1 QV1.2 QV1.5 QV1.6
+COINCELL: JRTC1.1 PR1.1
+DC_IN: PC22.1 PC731.1 PD705.2 PL4.2 PQ709.5 PR16.1 PR710.2
+DC_IN_SS: PC730.1 PQ708.4 PQ709.1 PQ709.2 PQ709.3 PQ710.1 PQ710.2 PQ710.3 PR730.1
+DCIN: PC709.1 PR708.2 PU700.28
+DCIN_JACK: PC9.1 PC21.1 PJPDC1.3 PJPDC1.4 PL4.1
+DCPRRTC: CC52.1 UC1.AE7
+DIMM1_VREF_DQ: CD1.1 CD5.1 JDIMM1.1 RD4.2 RD5.1 RD6.1
+DIMM2_VREF_DQ: CD33.1 CD34.1 JDIMM2.1 RD22.2 RD23.1 RD24.1
+EDP_VDD: PJP29.2 UV24.1
+LCDVDD: CV9.1 JEDP1.30 JEDP1.31 PJP29.1
+MIC1_VREF_OUT: DA4.2 DA5.2 UA1.30
+PBATT: PD703.2 PD703.3 PD704.2 PL1.2 PL2.2 PQ701.5 PQ701.6 PQ701.7 PQ701.8 PR723.2
+PCH_ASATA3PLL: CC55.1 CC56.1 LC2.2 RC17.2 UC1.A12 UC1.B11
+PCH_AUSB3PLL: CC47.1 CC51.1 LC1.2 RC149.1 UC1.B18 UC1.B27
+PCH_RTC_VCCSUS3_3: CC73.1 RC212.2 RC213.2 UC1.AH11
+PCH_VCC1P05: CC77.1 CC78.1 LC4.2 UC1.J18 UC1.K19
+PCH_VCCACLKPLL: CC81.1 CC82.1 LC5.2 RC69.2 UC1.A20
+PCH_VCCDSW: CC97.2 RC211.2 UC1.AG19 UC1.AG20
+PCH_VCCDSW3_3: CC80.1 CC97.1 JAPS1.3 JAPS1.7 RC92.1 RC153.2 RC216.2 RC217.2 RPC1.1 RPC1.2 RPC1.3 RPC1.4 UC1.AH10
+PCH_VCCDSW_R: CC65.1 RC211.1
+PWR_SRC: CC95.1 CV11.1 PC704.1 PC705.1 PC706.1 PC707.1 PC708.1 PJP100.1 PJP200.1 PJP302.1 PJP500.1 PL100.1 PL501.1 PL701.1 PR721.4 QV1.4 RV4.1
+PWR_SRC_AC: PJP700.1 PL700.2 PR701.1
+RSVD_VCC3P3_1: RL6.2 UL1.1
+RTC_CELL: CC49.1 CC50.1 PC1.1 PD3.1 RA21.1 RC1.1 RC8.1 RC9.1 RC10.1 RC78.2 RE31.1 RE32.1 RPE5.5 RPE5.6 RPE5.7 UC1.AG10
+RTC_CELL_VBAT: CE11.1 RE32.2 UE2.B64
+SD_IO_LDO: CR14.2 CR15.2 UR1.25
+SDC_IN: PC734.1 PQ710.5 PR701.4
+SM_VREF_CA: CD36.1 RD19.2 UC1.AP49
+SM_VREF_CA_DIMM: CD22.1 CD23.1 CD55.1 CD56.1 JDIMM1.126 JDIMM2.126 RD18.2 RD19.1 RD20.1
+SM_VREF_DQ0: CD21.1 RD5.2 UC1.AR51
+SM_VREF_DQ1: CD54.1 RD23.2 UC1.AP51
+USB_LEFT_PWR: CI1.1 CI3.1 JUSB1.1 UI1.6 UI1.7 UI1.8
+USB_RIGHT_PWR: CI8.1 CI10.1 JUSB2.1 UI2.6 UI2.7 UI2.8
+V_DDR_REF: PC212.1 PU200.4
+VCHGR: PC722.1 PC723.1 PC724.1 PC725.1 PD703.1 PQ701.1 PQ701.2 PQ701.3 PR721.1
+VDISPLAY_VCC: CV509.1 JMDP1.20 UV501.3
+VHDMI_VCC: CV26.1 CV27.1 JHDMI1.18 RV7.2 RV9.2 UV2.3
+VLDOIN_1.35V: PJP201.1 PU200.19
+VR_CAP: CE31.1 UE2.B12
+VREFOUT: CA26.1 RA5.2 RA6.2 UA1.23
+Z4012: PD3.2 PR1.2
-DCIN_JACK: PJP1.1 PJPDC1.1 PJPDC1.2
A_ON: RPE10.3 RZ42.1 UE2.A4 UZ8.3
AC_DIS: PQ708.5 PQ711.2 PR709.1 UE2.A10
AC_PRESENT: RPC1.6 UC1.AJ8 UE2.A54
ACAV_IN: PR713.2 PR714.1 PR715.1 RE278.2 UE2.A64
ACAV_IN_NB: RE278.1 UE2.B20
ALW_PWRGD_3V_5V: PR108.1 RE283.2 RZ51.1
ALW_PWRGD_3V_5V_EC: RE283.1 UE2.A1
ALWON: PR113.1 UE2.A60
AUD_HP_NB_SENSE: CA41.1 DA2.3 JHP1.6 QA1.2 RA2.1 UE3.2
AUD_HP_OUT_L: CA43.2 LA2.1 RA7.2 RA24.1
AUD_HP_OUT_L1: CA3.1 DA3.3 JHP1.1 LA2.2
AUD_HP_OUT_R: CA44.2 LA3.1 RA8.2 RA25.1
AUD_HP_OUT_R1: CA2.1 DA1.2 JHP1.2 LA3.2
AUD_NB_MUTE#: CA31.1 QA2.2 RA18.2 UA1.48 UE3.3
AUD_OUT_L: RA7.1 UA1.33
AUD_OUT_R: RA8.1 UA1.32
AUD_PC_BEEP: CA27.2 CA28.2 UA1.12
AUD_SENSE_A: QA1.1 UA1.13
AUX_EN_WOWL: RZ38.2 UE3.6 UZ3.3 UZ11.1
B-RAMP: PR502.2 PR507.1 PU500.11
BAT1_LED#: RZ28.1 UE2.B1
BAT2_LED#: RZ25.1 UE2.A55
BATDRV#: PQ701.4 PR722.2
BATT_WHITE#: JLED1.5 RZ25.2
BATT_YELLOW#: JLED1.4 RZ28.2
BBS_BIT: T109.1(TP-1) UC1.L8
BC_CLK_ECE1099: UE2.A43 UE3.33
BC_CLK_ECE1117: JKBTP1.7 UE2.A20
BC_DAT_ECE1099: RE36.2 UE2.B45 UE3.32
BC_DAT_ECE1117: JKBTP1.9 RPE5.1 UE2.B21
BC_INT#_ECE1099: UE2.A42 UE3.34
BC_INT#_ECE1117: JKBTP1.10 UE2.A19
BEEP: RA13.2 UE2.B19
BIA_PWM: DV1.1 LV1.2 RV1.1
BIA_PWM_EC: DV1.2 UE2.B25
BOARD_ID: CE40.1 RE79.2 UE2.B10
BOOT_1.35V: PR200.2 PU200.18
BOOT_1.35V_C: PC204.1 PR200.1
BQ24770_REGN: PC710.1 PR713.1 PR725.1 PR799.2 PU700.24
BREATH_LED#: QZ7.4 RZ34.1 UE2.B57
BREATH_LED#_Q: QZ7.3 RZ32.1
BREATH_WHITE_LED#: JLED1.2 RZ34.2
BREATH_WHITE_LED_SNIFF#: LED3.1 RZ32.2
BST_3V: PR110.2 PU100.9
BST_3V_C: PC109.2 PR110.1
BST_5V: PR109.1 PU100.17
BST_5V_C: PC110.1 PR109.2
BST_+V1.05SP: PC302.1 PU300.6
BST_+V1.05SP_C: PC302.2 PR312.1
BT_LED#: JNGFF1.8 QZ2.4 RZ15.1
BT_RADIO_DIS#: DZ2.1 RE11.2 UE3.12
BT_RADIO_DIS#_R: DZ2.2 JNGFF1.46
CAM_MIC_CBL_DET#: JEDP1.14 RPC16.5 UC1.F4
CFG0: JXDP1.9 RC183.1 UC1.AC60
CFG1: JXDP1.11 RC184.1 UC1.AC62
CFG2: JXDP1.15 UC1.AC63
CFG3: JXDP1.17 RC113.2 RC305.1 UC1.AA63
CFG3_R: JXDP1.60 RC113.1
CFG4: JXDP1.27 RC191.1 UC1.AA60
CFG5: JXDP1.29 UC1.Y62
CFG6: JXDP1.33 UC1.Y61
CFG7: JXDP1.35 UC1.Y60
CFG8: JXDP1.10 RC190.1 UC1.V62
CFG9: JXDP1.12 RC189.1 UC1.V61
CFG10: JXDP1.16 RC188.1 UC1.V60
CFG11: JXDP1.18 UC1.U60
CFG12: JXDP1.28 UC1.T63
CFG13: JXDP1.30 UC1.T62
CFG14: JXDP1.34 UC1.T61
CFG15: JXDP1.36 UC1.T60
CFG16: JXDP1.6 UC1.AA62
CFG17: JXDP1.4 UC1.AA61
CFG18: JXDP1.24 UC1.U63
CFG19: JXDP1.22 UC1.U62
CFG_RCOMP: RC185.1 UC1.V63
CHAGER_SRC: PC713.1 PC714.1 PC715.1 PC716.1 PC717.1 PJP700.2 PL700.1 PQ705.2
CHARGER_SMBCLK: PT2.1(TP-1) PU700.12 RPE6.3 UE2.B50
